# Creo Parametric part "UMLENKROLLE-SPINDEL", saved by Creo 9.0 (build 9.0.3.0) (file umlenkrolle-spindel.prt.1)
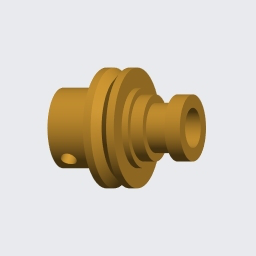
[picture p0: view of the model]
Units: millimeter Kilogram Sec (mmKs); MM, KILOGRAM, SECS
Materials in the file: STAHL

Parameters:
  WERKSTOFF = "Stahl"
  ERSTELLER = "ARINDA"
  BENENNUNG = "XXX"
  TEILETYP = "K"
  PTC_MASTER_MATERIAL = "STAHL"
  SCHRAUBEN_GROESSE = "M3x.5"
  METRISCH = "JA"

Other parameters: MASSE, STEIGUNG, BOHR_DURCHM, GEWINDEDURCHMESSER, GEWINDEGÄNGE_PRO_INCH, GEWINDETIEFE, GEWINDELÄNGE

Created from: ARINDA_STARTTEIL.PRT

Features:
  1. coordinate system
  2. datum plane "RECHTS_Y-Z"
  3. datum plane "OBEN_X-Z"
  4. datum plane "VORNE_X-Y"
  5. datum axis
  6. datum axis
  7. datum axis
  8. datum point "PNT0"
  9. revolve "Drehen 1"
  10. hole "Bohrung 1"
  11. extrusion "Profil 1"

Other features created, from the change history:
  coordinate system "CS1"

Other named items: LOGO, A_X, A_Y, A_Z, CS0

Layers: 01_ACHSEN, 01_ACHSEN_STD, 01_EBENEN_STD, 01_KOORDSYS_STD, 01_PUNKTE_STD, GEWINDE, SAMMELFLÄCHEN, VOLUMENGEOMETRIE

Notes: M3x.5 | GEWINDEBOHREN | 4.000 |  BOHREN (  | 2.500 | DURCH |   -(  |  ) BOHRUNG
